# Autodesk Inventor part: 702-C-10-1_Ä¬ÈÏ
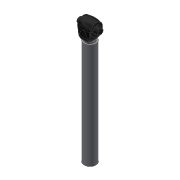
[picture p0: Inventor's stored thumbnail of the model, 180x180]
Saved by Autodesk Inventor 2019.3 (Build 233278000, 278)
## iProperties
Created: 2010-06
Part Number: 702-C-10-1_Ä¬ÈÏ
Material: Ogólny
Document SubType Name: Modeling
Designer: CADENGINEERING4
Density: 1 g/cm^3
Appearance: Domyślna
Author: CADENGINEERING4
Revision Number: ÈÎºÎ
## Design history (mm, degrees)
feature "NONE"
feature "NONE:1"
node "Bryła1"
node "Bryła2"
